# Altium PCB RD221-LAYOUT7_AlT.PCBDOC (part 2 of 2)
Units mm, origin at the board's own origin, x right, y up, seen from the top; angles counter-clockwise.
Board outline 85 x 108 mm, 4 copper layers (TOP, Mid-Layer 1, Mid-Layer 2, BOTTOM), stack 0.711 mm thick; 92 components, 59 nets, 620 pads, 607 vias.
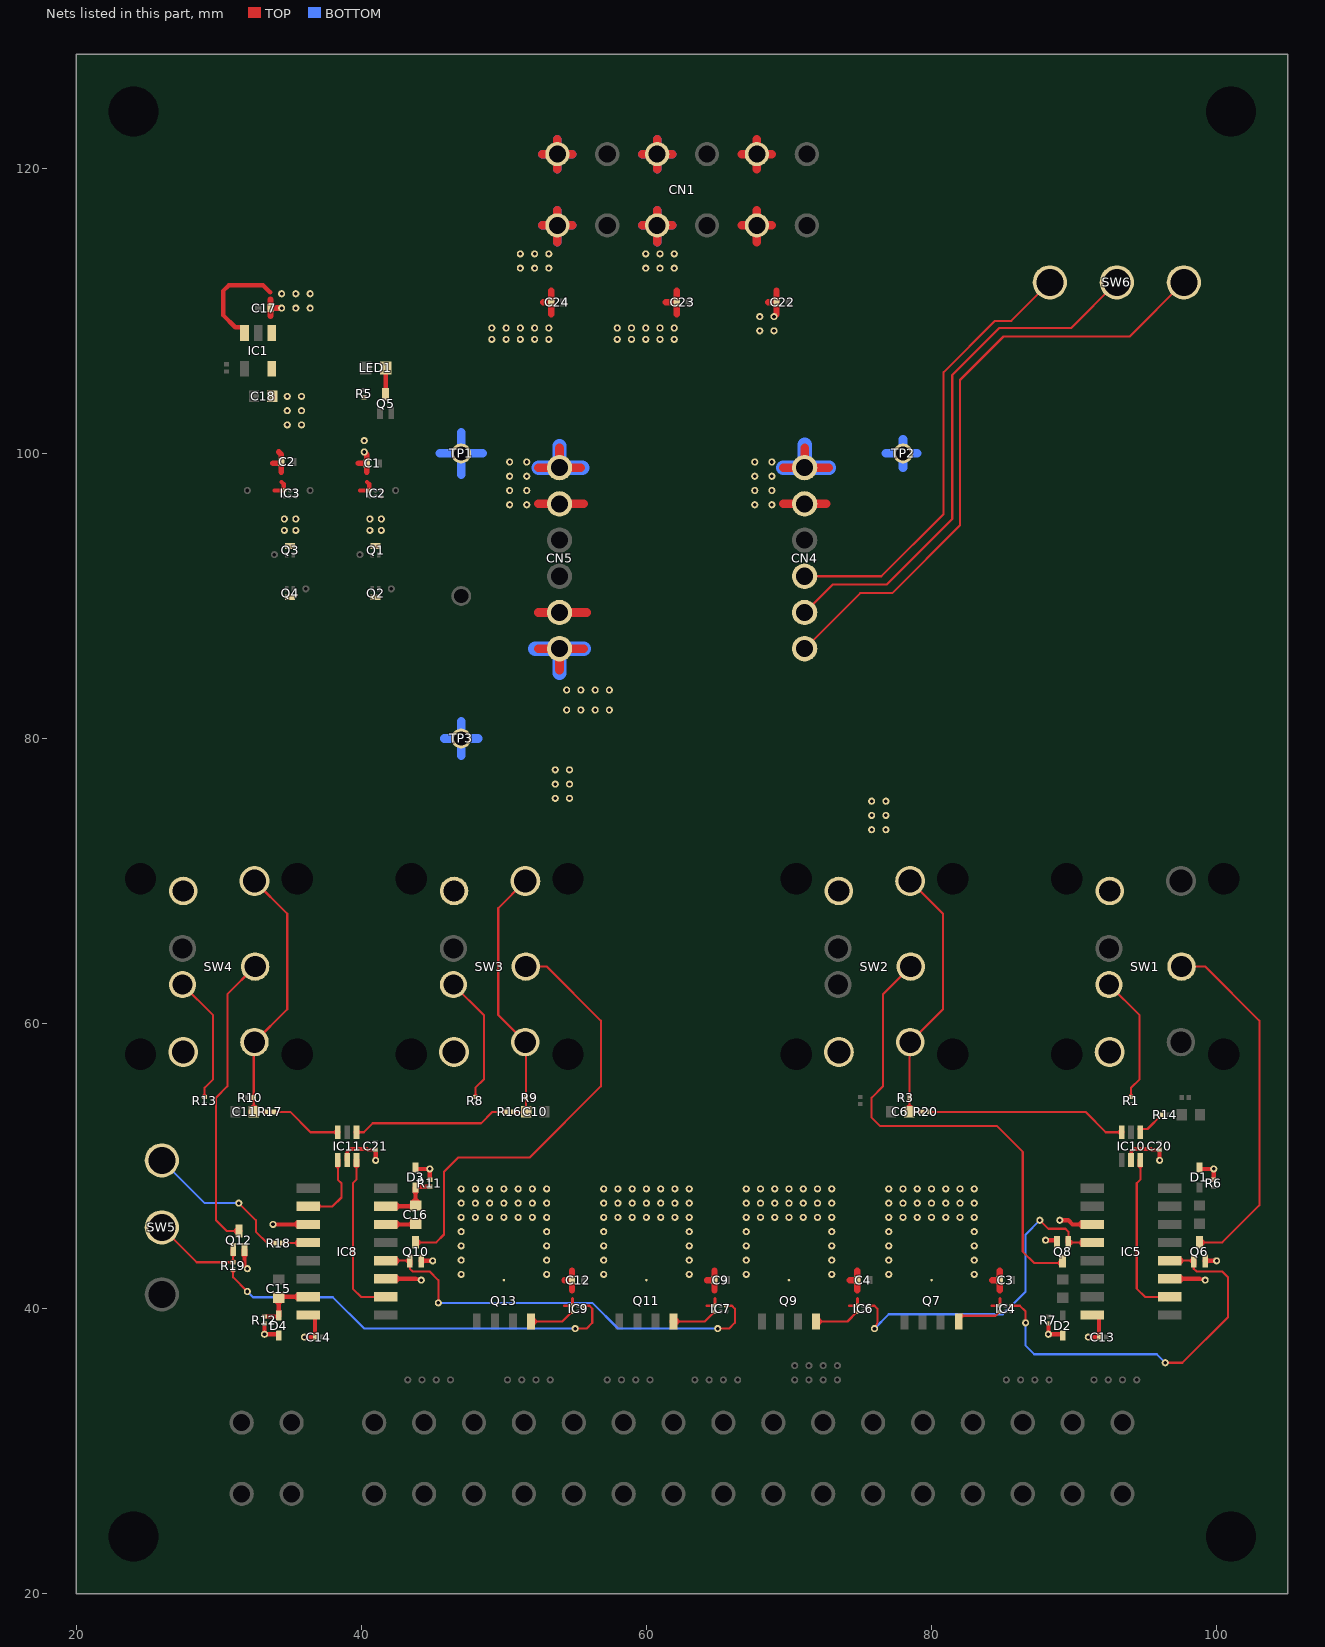
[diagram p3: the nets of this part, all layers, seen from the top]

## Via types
v1: diameter 0.6, hole 0.25, TOP to BOTTOM, 607 vias

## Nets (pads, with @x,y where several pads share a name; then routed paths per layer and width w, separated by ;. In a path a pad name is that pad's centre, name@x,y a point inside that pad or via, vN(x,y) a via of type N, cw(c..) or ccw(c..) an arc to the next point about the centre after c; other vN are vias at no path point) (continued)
SIG313: C6.1 R3.1 R20.1 SW2.2 SW2.4 | length 19
  TOP w0.15: C6.1@78.45,53.964 R3.1@78.45,54.704 ; R3.1@78.45,54.896 78.45,57.4 SW2.2@78.5,58.7 80.8,61 80.8,67.7 SW2.4@78.5,70 ; C6.1@78.554,53.8 R20.1@79.254,53.8
  TOP w0.3: R3.1@78.45,54.704 R3.1@78.45,54.8 R3.1@78.45,54.896 ; R20.1@79.254,53.8 R20.1@79.35,53.8
  TOP w0.7: C6.1@78.44,53.8 C6.1@78.554,53.8 ; C6.1@78.45,53.81 C6.1@78.45,53.964
SIG315: C10.1 R9.1 R16.2 SW3.2 SW3.4 | length 18.7
  TOP w0.15: R16.2@50.746,53.8 C10.1@51.56,53.8 R9.1@51.55,54.8 ; SW3.4@51.5,70 49.6,68.1 49.6,60.6 SW3.2@51.5,58.7 51.55,57.4 R9.1@51.55,54.896
  TOP w0.3: R16.2@50.65,53.8 R16.2@50.746,53.8 ; R9.1@51.55,54.8 R9.1@51.55,54.896
SIG318: C16.1 D3.A IC8.7 R11.2 | length 4.3
  TOP w0.3: IC8.7@42.418,47.175 C16.1@43.594,47.175 ; C16.1@43.8,47.416 D3.A@43.8,48.186 ; D3.A@43.8,48.55 R11.2@44.8,48.55
  TOP w0.4: D3.A@43.8,48.186 D3.A@43.8,48.5
  TOP w0.55: C16.1@43.594,47.175 C16.1@43.8,47.175
  TOP w0.6: IC8.7@41.725,47.175 IC8.7@42.418,47.175
  TOP w0.7: C16.1@43.8,47.24 C16.1@43.8,47.416
SIG321: C16.2 IC8.6 | length 2.1
  TOP w0.3: IC8.6@42.418,45.905 C16.2@43.602,45.905
  TOP w0.6: IC8.6@41.725,45.905 IC8.6@42.418,45.905 ; C16.2@43.602,45.905 C16.2@43.8,45.905
SIG324: IC8.10 IC11.4 | length 5.3
  TOP w0.15: IC8.10@36.868,47.175 37.975,47.175 38.6,47.8 38.6,48.8 38.35,49.05 IC11.4@38.35,50.039
  TOP w0.4: IC11.4@38.35,50.039 IC11.4@38.35,50.425
  TOP w0.6: IC8.10@36.275,47.175 IC8.10@36.868,47.175
SIG326: R13.1 SW4.L2 | length 9
  TOP w0.15: SW4.L2@27.45,62.73 29.6,60.58 29.6,56.097 29,55.497 R13.1@29,54.946
  TOP w0.3: R13.1@29,54.85 R13.1@29,54.946
SIG328: R8.1 SW3.L2 | length 9
  TOP w0.15: SW3.L2@46.45,62.73 48.6,60.58 48.6,56.097 48,55.497 R8.1@48,54.946
  TOP w0.3: R8.1@48,54.85 R8.1@48,54.946
SIG332: C15.2 D4.A IC8.15 R12.2 | length 4.3
  TOP w0.3: R12.2@33.2,39.45 D4.A@34.2,39.45 ; D4.A@34.2,39.814 C15.2@34.2,40.62 ; C15.2@34.406,40.825 IC8.15@35.582,40.825
  TOP w0.4: D4.A@34.2,39.5 D4.A@34.2,39.814
  TOP w0.55: C15.2@34.2,40.825 C15.2@34.406,40.825
  TOP w0.6: IC8.15@35.582,40.825 IC8.15@36.275,40.825
  TOP w0.7: C15.2@34.2,40.62 C15.2@34.2,40.76
SIG333: C11.1 R10.1 R17.1 SW4.2 SW4.4 | length 19
  TOP w0.15: C11.1@32.45,53.964 R10.1@32.45,54.704 ; R10.1@32.45,54.896 32.45,57.4 SW4.2@32.5,58.7 34.8,61 34.8,67.7 SW4.4@32.5,70 ; C11.1@32.554,53.8 R17.1@33.254,53.8
  TOP w0.3: R10.1@32.45,54.704 R10.1@32.45,54.8 R10.1@32.45,54.896 ; R17.1@33.254,53.8 R17.1@33.35,53.8
  TOP w0.7: C11.1@32.44,53.8 C11.1@32.554,53.8 ; C11.1@32.45,53.81 C11.1@32.45,53.964
SIG335: IC8.12 R18.2 | length 1.8
  TOP w0.15: R18.2@34.546,44.6 IC8.12@35.608,44.6
  TOP w0.3: R18.2@34.45,44.6 R18.2@34.546,44.6
  TOP w0.55: IC8.12@35.608,44.6 IC8.12@36.275,44.6
SIG338: IC7.A1 Q11.4 | length 3.2
  TOP w0.15: Q11.4@62.037,39.1 64.1,39.1 IC7.A1@64.8,39.8
  TOP w0.55: Q11.4@61.905,39.1 Q11.4@62.037,39.1
SIG339: IC6.A1 Q9.4 | length 3.2
  TOP w0.15: Q9.4@72.037,39.1 74.1,39.1 IC6.A1@74.8,39.8
  TOP w0.55: Q9.4@71.905,39.1 Q9.4@72.037,39.1
SIG340: IC4.A1 Q7.4 | length 3
  TOP w0.15: Q7.4@82.126,39.5 84.5,39.5 IC4.A1@84.8,39.8
  TOP w0.3: Q7.4@81.905,39.5 Q7.4@82.126,39.5
SIG341: IC9.A1 Q13.4 | length 3.2
  TOP w0.15: Q13.4@52.037,39.1 54.1,39.1 IC9.A1@54.8,39.8
  TOP w0.55: Q13.4@51.905,39.1 Q13.4@52.037,39.1
SIG345: IC10.3 R20.2 | length 14.1
  TOP w0.15: R20.2@79.946,53.8 90.8,53.8 92.225,52.375 IC10.3@93.255,52.375
  TOP w0.3: R20.2@79.85,53.8 R20.2@79.946,53.8
  TOP w0.4: IC10.3@93.255,52.375 IC10.3@93.35,52.375
SIG347: IC9.C2 pad.@32,41.2 pad.@55,38.6 R19.2 | length 29.1
  TOP w0.15: R19.2@31,42.654 31,42.2 pad.@32,41.2 ; pad.@55,38.6 55.8,38.6 56.2,39 56.2,40 56,40.2 IC9.C2@55.6,40.2
  TOP w0.3: R19.2@31,42.654 R19.2@31,42.75
  BOTTOM w0.15: pad.@32,41.2 32.4,40.8 38,40.8 40.2,38.6 pad.@55,38.6
SIG348: pad.@31.4,47.4 R18.1 SW5.1 | length 10.8
  TOP w0.15: pad.@31.4,47.4 32.6,46.2 32.6,45.4 33.4,44.6 R18.1@33.854,44.6
  TOP w0.3: R18.1@33.854,44.6 R18.1@33.95,44.6
  BOTTOM w0.15: SW5.1@26,50.4 29,47.4 pad.@31.4,47.4
SIG3334: LED1.C Q5.C | length 1.8
  TOP w0.3: Q5.C@41.7,104.15 LED1.C@41.7,106
SIG3335: Q6.C SW1.LC | length 25.3
  TOP w0.15: SW1.LC@97.54,64 99.2,64 103,60.2 103,47.25 100.4,44.65 Q6.C@98.925,44.65
  TOP w0.5: Q6.C@98.8,44.65 Q6.C@98.925,44.65
SIG3337: Q8.C SW2.LC | length 33.5
  TOP w0.15: SW2.LC@78.54,64 76.6,62.06 76.6,55.6 75.8,54.8 75.8,53.4 76.4,52.8 84.6,52.8 86.4,51 86.4,44 87.2,43.2 Q8.C@89.075,43.2
  TOP w0.5: Q8.C@89.075,43.2 Q8.C@89.2,43.2
SIG3338: Q10.C SW3.LC | length 31.5
  TOP w0.15: Q10.C@43.925,44.65 45.25,44.65 45.8,45.2 45.8,49.6 46.8,50.6 51.8,50.6 56.8,55.6 56.8,60.2 53,64 SW3.LC@51.54,64
  TOP w0.5: Q10.C@43.8,44.65 Q10.C@43.925,44.65
SIG3340: Q12.C SW4.LC | length 20.8
  TOP w0.15: Q12.C@31.275,45.45 30.55,45.45 29.8,46.2 29.8,54.8 30.6,55.6 30.6,62.06 SW4.LC@32.54,64
  TOP w0.5: Q12.C@31.275,45.45 Q12.C@31.4,45.45
SIG3348: R1.1 SW1.L2 | length 9
  TOP w0.15: SW1.L2@92.45,62.73 94.6,60.58 94.6,56.097 94,55.497 R1.1@94,54.946
  TOP w0.3: R1.1@94,54.85 R1.1@94,54.946
SIG3352: IC5.2 IC10.6 | length 11.7
  TOP w0.15: IC10.6@94.65,50.039 94.65,49.05 94.4,48.8 94.4,41.4 94.975,40.825 IC5.2@96.225,40.825
  TOP w0.4: IC10.6@94.65,50.039 IC10.6@94.65,50.425
  TOP w0.6: IC5.2@96.225,40.825 IC5.2@96.725,40.825
SIG3353: IC10.1 R14.1 | length 2
  TOP w0.15: IC10.1@94.715,52.6 95.15,52.6 R14.1@96.15,53.6
  TOP w0.3: IC10.1@94.6,52.6 IC10.1@94.715,52.6
SIG3354: IC8.2 IC11.6 | length 11.7
  TOP w0.15: IC11.6@39.65,50.039 39.65,49.05 39.4,48.8 39.4,41.4 39.975,40.825 IC8.2@41.225,40.825
  TOP w0.4: IC11.6@39.65,50.039 IC11.6@39.65,50.425
  TOP w0.6: IC8.2@41.225,40.825 IC8.2@41.725,40.825
SIG3355: IC11.1 R16.1 | length 11.1
  TOP w0.15: IC11.1@39.745,52.375 40.175,52.375 40.8,53 48.4,53 49.2,53.8 R16.1@50.054,53.8
  TOP w0.3: R16.1@50.054,53.8 R16.1@50.15,53.8
  TOP w0.4: IC11.1@39.65,52.375 IC11.1@39.745,52.375
SIG3356: IC11.3 R17.2 | length 5.1
  TOP w0.15: R17.2@33.946,53.8 35,53.8 36.425,52.375 IC11.3@38.239,52.375
  TOP w0.3: R17.2@33.85,53.8 R17.2@33.946,53.8
  TOP w0.4: IC11.3@38.239,52.375 IC11.3@38.35,52.375
SIG3359: CN4.3 SW6.3 | length 31.6
  TOP w0.15: CN4.3@71.1,91.38 76.48,91.38 80.85,95.75 80.85,105.7 84.45,109.3 85.6,109.3 SW6.3@88.3,112
SIG3360: CN4.2 SW6.2 | length 37.4
  TOP w0.15: CN4.2@71.1,88.84 73.06,90.8 76.85,90.8 81.45,95.4 81.45,105.5 84.75,108.8 89.8,108.8 SW6.2@93,112
SIG3361: CN4.1 SW6.1 | length 43.2
  TOP w0.15: CN4.1@71.1,86.3 75,90.2 77.25,90.2 82,94.95 82,105.15 85.05,108.2 93.9,108.2 SW6.1@97.7,112
SW_CONTA: IC4.C2 IC5.4 pad.@86.6,39 pad.@96.4,36.2 Q6.B | length 27.2
  TOP w0.15: IC4.C2@85.6,40.2 86.2,40.2 86.6,39.8 pad.@86.6,39 ; pad.@96.4,36.2 97.6,36.2 100.8,39.4 100.8,42.2 100.4,42.6 98.6,42.6 98.4,42.8 Q6.B@98.4,43.1 ; IC5.4@97.364,43.365 Q6.B@98.279,43.365
  TOP w0.37: Q6.B@98.279,43.365 Q6.B@98.385,43.365
  TOP w0.4: Q6.B@98.4,43.1 Q6.B@98.4,43.35
  TOP w0.6: IC5.4@96.725,43.365 IC5.4@97.364,43.365
  BOTTOM w0.15: pad.@86.6,39 86.6,37.4 87.2,36.8 95.8,36.8 pad.@96.4,36.2
SW_CONTB: IC5.12 IC6.C2 pad.@76,38.6 pad.@87.6,46.2 Q8.B | length 24
  TOP w0.15: IC6.C2@75.6,40.2 76,40.2 76.2,40 76.2,39 pad.@76,38.6 ; pad.@87.6,46.2 88.2,45.6 89.4,45.6 89.6,45.4 Q8.B@89.6,44.9 ; Q8.B@89.711,44.635 IC5.12@90.636,44.635
  TOP w0.4: Q8.B@89.6,44.635 Q8.B@89.711,44.635 ; Q8.B@89.6,44.65 Q8.B@89.6,44.9
  TOP w0.6: IC5.12@90.636,44.635 IC5.12@91.275,44.635
  BOTTOM w0.15: pad.@76,38.6 77,39.6 85,39.6 86.6,41.2 86.6,45.2 pad.@87.6,46.2
SW_CONTC: IC7.C2 IC8.4 pad.@45.4,40.4 pad.@65,38.6 Q10.B | length 29.6
  TOP w0.15: IC8.4@42.364,43.365 Q10.B@43.289,43.365 ; Q10.B@43.4,43.1 43.4,42.8 43.6,42.6 44.8,42.6 45.4,42 pad.@45.4,40.4 ; pad.@65,38.6 65.8,38.6 66.2,39 66.2,40 66,40.2 IC7.C2@65.6,40.2
  TOP w0.4: Q10.B@43.289,43.365 Q10.B@43.4,43.365 ; Q10.B@43.4,43.1 Q10.B@43.4,43.35
  TOP w0.6: IC8.4@41.725,43.365 IC8.4@42.364,43.365
  BOTTOM w0.15: pad.@45.4,40.4 56.2,40.4 58,38.6 pad.@65,38.6
SW_CONTD: Q12.B R19.1 SW5.2 | length 6.9
  TOP w0.15: SW5.2@26,45.7 28.45,43.25 R19.1@30.904,43.25 ; R19.1@31,43.346 Q12.B@31,43.836
  TOP w0.3: R19.1@30.904,43.25 R19.1@31,43.25 R19.1@31,43.346
  TOP w0.4: Q12.B@31,43.836 Q12.B@31,44.15
VDD: C17.1 C22.1 CN1.5 CN1.5A IC1.1 IC1.3 pad.@34.4,110.2 pad.@34.4,111.2 pad.@35.4,110.2 pad.@35.4,111.2 pad.@36.4,110.2 pad.@36.4,111.2 pad.@67.95,108.6 pad.@67.95,109.6 pad.@68.95,108.6 pad.@68.95,109.6 | length 19.9
  TOP w0.3: IC1.3@31.78,108.85 31.15,108.85 30.3,109.7 30.3,111.4 30.7,111.8 33.1,111.8 33.6,111.3
  TOP w0.45: 33.625,109.65 C17.1@33.625,110.2 ; 33.625,110.8 C17.1@33.625,110.2 ; pad.@34.4,110.2 C17.1@33.625,110.2 ; 68.55,110.6 C22.1@69.125,110.6 ; pad.@69.125,109.775 C22.1@69.125,110.6 ; 69.125,111.425 C22.1@69.125,110.6
  TOP w0.6: 66.7,116 CN1.5@67.75,116 ; 66.7,121 CN1.5A@67.75,121 ; 67.75,114.8 CN1.5@67.75,116 ; 67.75,117.05 CN1.5@67.75,116 ; 67.75,119.95 CN1.5A@67.75,121 ; 67.75,122.05 CN1.5A@67.75,121 ; 68.8,116 CN1.5@67.75,116 ; 68.8,121 CN1.5A@67.75,121
VINA: C1.1 C24.1 CN1.1 CN1.1A CN5.1 CN5.2 IC2.A2 pad.@40.2,100.1 pad.@40.2,100.9 pad.@40.6,94.6 pad.@40.6,95.4 pad.@41.4,94.6 pad.@41.4,95.4 pad.@49.15,108 pad.@49.15,108.8 pad.@50.4,96.4 pad.@50.4,97.4 pad.@50.4,98.4 pad.@50.4,99.4 pad.@50.15,108 pad.@50.15,108.8 pad.@51.6,96.4 pad.@51.6,97.4 pad.@51.6,98.4 pad.@51.6,99.4 pad.@51.15,108 pad.@51.15,108.8 pad.@51.15,113 pad.@51.15,114 pad.@52.15,108 pad.@52.15,108.8 pad.@52.15,113 pad.@52.15,114 pad.@53.15,108 pad.@53.15,108.8 pad.@53.15,113 pad.@53.15,114 Q1.D TP1.1 | length 40.9
  TOP w0.3: 39.9,97.4 IC2.A2@40.6,97.4 40.55,97.45 40.55,97.85 40.4,98
  TOP w0.4: 39.8,99.3 C1.1@40.375,99.3 ; pad.@40.2,100.1 40.375,99.925 C1.1@40.375,99.3 ; 40.375,98.7 C1.1@40.375,99.3
  TOP w0.45: 52.75,110.6 C24.1@53.325,110.6 ; 53.325,109.775 C24.1@53.325,110.6 ; 53.325,111.425 C24.1@53.325,110.6
  TOP w0.6: 52.4,96.46 CN5.2@53.9,96.46 55.6,96.46 ; 52.4,99 CN5.1@53.9,99 ; 52.7,116 CN1.1@53.75,116 ; 52.7,121 CN1.1A@53.75,121 ; 53.75,114.8 CN1.1@53.75,116 ; 53.75,117.05 CN1.1@53.75,116 ; 53.75,119.95 CN1.1A@53.75,121 ; 53.75,122.05 CN1.1A@53.75,121 ; 53.9,100.4 CN5.1@53.9,99 ; 54.8,116 CN1.1@53.75,116 ; 54.8,121 CN1.1A@53.75,121 ; 55.4,99 CN5.1@53.9,99
  BOTTOM w0.6: 45.5,100 TP1.1@47,100 ; 47,98.5 TP1.1@47,100 ; 47,101.5 TP1.1@47,100 ; 48.5,100 TP1.1@47,100 ; 52.7,116 CN1.1@53.75,116 ; 52.7,121 CN1.1A@53.75,121 ; 53.75,114.8 CN1.1@53.75,116 ; 53.75,117.05 CN1.1@53.75,116 ; 53.75,119.95 CN1.1A@53.75,121 ; 53.75,122.05 CN1.1A@53.75,121 ; 54.8,116 CN1.1@53.75,116 ; 54.8,121 CN1.1A@53.75,121
  BOTTOM w1: 52.45,99 CN5.1@53.9,99 ; 53.9,100.525 CN5.1@53.9,99 ; 55.5,99 CN5.1@53.9,99
VINB: C23.1 CN1.3 CN1.3A CN4.5 CN4.6 pad.@57.95,108 pad.@57.95,108.8 pad.@58.95,108 pad.@58.95,108.8 pad.@59.95,108 pad.@59.95,108.8 pad.@59.95,113 pad.@59.95,114 pad.@60.95,108 pad.@60.95,108.8 pad.@60.95,113 pad.@60.95,114 pad.@61.95,108 pad.@61.95,108.8 pad.@61.95,113 pad.@61.95,114 pad.@67.6,96.4 pad.@67.6,97.4 pad.@67.6,98.4 pad.@67.6,99.4 pad.@68.8,96.4 pad.@68.8,97.4 pad.@68.8,98.4 pad.@68.8,99.4 TP2.1 | length 36.1
  TOP w0.45: 61.35,110.6 C23.1@62.125,110.6 ; 62.125,109.775 C23.1@62.125,110.6 ; 62.125,111.425 C23.1@62.125,110.6
  TOP w0.6: 59.7,116 CN1.3@60.75,116 ; 59.7,121 CN1.3A@60.75,121 ; 60.75,114.8 CN1.3@60.75,116 ; 60.75,117.05 CN1.3@60.75,116 ; 60.75,119.95 CN1.3A@60.75,121 ; 60.75,122.05 CN1.3A@60.75,121 ; 61.8,116 CN1.3@60.75,116 ; 61.8,121 CN1.3A@60.75,121 ; 69.6,96.46 CN4.5@71.1,96.46 72.6,96.46 ; 69.6,99 CN4.6@71.1,99 ; 71.1,100.4 CN4.6@71.1,99 ; 72.8,99 CN4.6@71.1,99
  BOTTOM w0.6: 59.7,116 CN1.3@60.75,116 ; 59.7,121 CN1.3A@60.75,121 ; 60.75,114.8 CN1.3@60.75,116 ; 60.75,117.05 CN1.3@60.75,116 ; 60.75,119.95 CN1.3A@60.75,121 ; 60.75,122.05 CN1.3A@60.75,121 ; 61.8,116 CN1.3@60.75,116 ; 61.8,121 CN1.3A@60.75,121 ; 76.8,100 TP2.1@78,100 ; 78,99 TP2.1@78,100 ; 78,101 TP2.1@78,100 ; 79,100 TP2.1@78,100
  BOTTOM w1: 69.6,99 CN4.6@71.1,99 ; 71.1,100.6 CN4.6@71.1,99 ; 72.8,99 CN4.6@71.1,99
VOUT: C3.1 C4.1 C9.1 C12.1 CN5.5 CN5.6 IC4.A2 IC6.A2 IC7.A2 IC9.A2 pad.@47,42.4 pad.@47,43.4 pad.@47,44.4 pad.@47,45.4 pad.@47,46.4 pad.@47,47.4 pad.@47,48.4 pad.@48,46.4 pad.@48,47.4 pad.@48,48.4 pad.@49,46.4 pad.@49,47.4 pad.@49,48.4 pad.@50,46.4 pad.@50,47.4 pad.@50,48.4 pad.@51,46.4 pad.@51,47.4 pad.@51,48.4 pad.@52,46.4 pad.@52,47.4 pad.@52,48.4 pad.@53,42.4 pad.@53,43.4 pad.@53,44.4 pad.@53,45.4 pad.@53,46.4 pad.@53,47.4 pad.@53,48.4 pad.@54.4,82 pad.@54.4,83.4 pad.@55.4,82 pad.@55.4,83.4 pad.@56.4,82 pad.@56.4,83.4 pad.@57,42.4 pad.@57,43.4 pad.@57,44.4 pad.@57,45.4 pad.@57,46.4 pad.@57,47.4 pad.@57,48.4 pad.@57.4,82 pad.@57.4,83.4 pad.@58,46.4 pad.@58,47.4 pad.@58,48.4 pad.@59,46.4 pad.@59,47.4 pad.@59,48.4 pad.@60,46.4 pad.@60,47.4 pad.@60,48.4 pad.@61,46.4 pad.@61,47.4 pad.@61,48.4 pad.@62,46.4 pad.@62,47.4 pad.@62,48.4 pad.@63,42.4 pad.@63,43.4 pad.@63,44.4 pad.@63,45.4 pad.@63,46.4 pad.@63,47.4 pad.@63,48.4 pad.@67,42.4 pad.@67,43.4 pad.@67,44.4 pad.@67,45.4 pad.@67,46.4 pad.@67,47.4 pad.@67,48.4 pad.@68,46.4 pad.@68,47.4 pad.@68,48.4 pad.@69,46.4 pad.@69,47.4 pad.@69,48.4 pad.@70,46.4 pad.@70,47.4 pad.@70,48.4 pad.@71,46.4 pad.@71,47.4 pad.@71,48.4 pad.@72,46.4 pad.@72,47.4 pad.@72,48.4 pad.@73,42.4 pad.@73,43.4 pad.@73,44.4 pad.@73,45.4 pad.@73,46.4 pad.@73,47.4 pad.@73,48.4 pad.@77,42.4 pad.@77,43.4 pad.@77,44.4 pad.@77,45.4 pad.@77,46.4 pad.@77,47.4 pad.@77,48.4 pad.@78,46.4 pad.@78,47.4 pad.@78,48.4 pad.@79,46.4 pad.@79,47.4 pad.@79,48.4 pad.@80,46.4 pad.@80,47.4 pad.@80,48.4 pad.@81,46.4 pad.@81,47.4 pad.@81,48.4 pad.@82,46.4 pad.@82,47.4 pad.@82,48.4 pad.@83,42.4 pad.@83,43.4 pad.@83,44.4 pad.@83,45.4 pad.@83,46.4 pad.@83,47.4 pad.@83,48.4 Q7.5 Q9.5 Q11.5 Q13.5 TP3.1 | length 29.7
  TOP w0.2: 54.25,40.2 IC9.A2@54.8,40.2 54.8,40.7 ; 64.25,40.2 IC7.A2@64.8,40.2 64.8,40.7 ; 74.25,40.2 IC6.A2@74.8,40.2 74.8,40.7 ; 84.25,40.2 IC4.A2@84.8,40.2 84.8,40.7
  TOP w0.45: 54.25,42 C12.1@54.775,42 ; 54.775,41.3 C12.1@54.775,42 ; 54.775,42.65 C12.1@54.775,42 ; 64.25,42 C9.1@64.775,42 ; 64.775,41.3 C9.1@64.775,42 ; 64.775,42.65 C9.1@64.775,42 ; 74.25,42 C4.1@74.775,42 ; 74.775,41.3 C4.1@74.775,42 ; 74.775,42.65 C4.1@74.775,42 ; 84.25,42 C3.1@84.775,42 ; 84.775,41.3 C3.1@84.775,42 ; 84.775,42.65 C3.1@84.775,42
  TOP w0.6: 52.4,86.3 CN5.6@53.9,86.3 ; 52.4,88.84 CN5.5@53.9,88.84 55.8,88.84 ; 53.9,84.8 CN5.6@53.9,86.3 ; 55.6,86.3 CN5.6@53.9,86.3
  BOTTOM w0.6: 45.8,80 TP3.1@47,80 ; 47,78.8 TP3.1@47,80 ; 47,81.2 TP3.1@47,80 ; 48.2,80 TP3.1@47,80
  BOTTOM w1: 52.2,86.3 CN5.6@53.9,86.3 ; 53.9,84.6 CN5.6@53.9,86.3 ; 55.6,86.3 CN5.6@53.9,86.3
VP_4R8: C2.1 C13.2 C14.2 C18.1 C20.2 C21.2 D1.C D2.C D3.C D4.C IC1.5 IC3.A2 IC5.3 IC5.11 IC5.16 IC8.3 IC8.11 IC8.16 IC10.5 IC11.5 pad.@32,42.8 pad.@33.2,38.2 pad.@33.8,45.905 pad.@34.6,94.6 pad.@34.6,95.4 pad.@34.8,102 pad.@34.8,103 pad.@34.8,104 pad.@35.4,94.6 pad.@35.4,95.4 pad.@35.8,102 pad.@35.8,103 pad.@35.8,104 pad.@36,38 pad.@41,50.4 pad.@44.2,42 pad.@44.8,49.8 pad.@45,43.35 pad.@53.6,75.8 pad.@53.6,76.8 pad.@53.6,77.8 pad.@54.6,75.8 pad.@54.6,76.8 pad.@54.6,77.8 pad.@75.8,73.6 pad.@75.8,74.6 pad.@75.8,75.6 pad.@76.8,73.6 pad.@76.8,74.6 pad.@76.8,75.6 pad.@88,44.8 pad.@88.2,38.2 pad.@89,46.2 pad.@91,38 pad.@96,50.4 pad.@99.2,42 pad.@99.8,49.8 pad.@100,43.35 Q3.D Q6.E Q8.E Q10.E Q12.E R5.2 R6.1 R7.1 R11.1 R12.1 SW1.1 SW1.3 SW2.1 SW2.3 SW3.1 SW3.3 SW4.1 SW4.3 | length 35.6
  TOP w0.25: IC11.5@39,50.7 39,51 39.2,51.2 40.4,51.2 40.45,51.15 C21.2@40.868,51.15 ; IC10.5@94,50.7 94,51 94.2,51.2 95.4,51.2 95.45,51.15 C20.2@95.868,51.15
  TOP w0.3: Q12.E@31.8,43.736 31.8,43 pad.@32,42.8 ; R12.1@33.2,38.95 pad.@33.2,38.2 D4.C@34.2,38.2 ; pad.@33.8,45.905 IC8.11@35.582,45.905 ; 33.9,97.4 IC3.A2@34.6,97.4 34.55,97.45 34.55,97.85 34.4,98 ; pad.@36,38 C14.2@36.75,38 IC8.16@36.75,39.555 ; C21.2@40.868,51.15 C21.2@41,51.15 pad.@41,50.4 ; IC8.3@42.418,42.095 43.8,42.095 43.859,42.081 pad.@44.2,42 ; D3.C@43.8,49.8 pad.@44.8,49.8 R11.1@44.8,49.05 ; Q10.E@44.364,43.35 pad.@45,43.35 ; pad.@88,44.8 Q8.E@88.8,44.8 ; R7.1@88.2,38.95 pad.@88.2,38.2 D2.C@89.2,38.2 ; pad.@89,46.2 89.6,46.2 89.895,45.905 IC5.11@90.582,45.905 ; pad.@91,38 C13.2@91.75,38 IC5.16@91.75,39.555 ; C20.2@95.868,51.15 C20.2@96,51.15 pad.@96,50.4 ; IC5.3@97.418,42.095 98.8,42.095 98.859,42.081 pad.@99.2,42 ; D1.C@98.8,49.8 pad.@99.8,49.8 R6.1@99.8,49.05 ; Q6.E@99.364,43.35 pad.@100,43.35
  TOP w0.4: Q12.E@31.8,43.736 Q12.E@31.8,44.15 ; 33.8,99.3 C2.1@34.375,99.3 ; 34.2,100.1 34.375,99.925 C2.1@34.375,99.4 C2.1@34.375,99.3 ; 34.375,98.7 C2.1@34.375,99.3 ; IC11.5@39,50.425 IC11.5@39,50.7 ; Q10.E@44.2,43.35 Q10.E@44.364,43.35 ; IC10.5@94,50.425 IC10.5@94,50.7 ; Q6.E@99.2,43.35 Q6.E@99.364,43.35
  TOP w0.6: IC8.11@35.582,45.905 IC8.11@36.275,45.905 ; IC8.3@41.725,42.095 IC8.3@42.418,42.095 ; IC5.11@90.582,45.905 IC5.11@91.275,45.905 ; IC5.3@96.725,42.095 IC5.3@97.418,42.095
VP_SW: Q2.D Q4.D
pads on no net: cam1. cam2. cam4. cam5. IC2.C1 IC3.C1 IC4.B1 IC4.C1 IC5.5 IC5.13 IC6.B1 IC6.C1 IC7.B1 IC7.C1 IC8.5 IC8.13 IC9.B1 IC9.C1 SW1. SW1.L1 SW2. SW2.L1 SW3. SW3.L1 SW4. SW4.L1

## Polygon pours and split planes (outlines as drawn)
no net on Top Overlay "TOPOVERLAY97" (solid, pour order 0): 24.6,80.2 23.6,81.2 25.6,81.2
no net on Top Overlay "TOPOVERLAY96" (solid, pour order 0): 24.6,83.4 25.6,82.4 23.6,82.4
no net on Top Overlay "TOPOVERLAY95" (solid, pour order 0): 94.306,102.487 93.306,101.487 93.306,103.487
no net on Top Overlay "TOPOVERLAY94" (solid, pour order 0): 91.206,102.487 92.206,103.487 92.206,101.487
no net on Top Overlay "TOPOVERLAY93" (solid, pour order 0): 53.1,104.9 54.9,104.9 54,103.1
no net on Top Overlay "TOPOVERLAY100" (solid, pour order 0): 97.688,91.502 98.51,94.216 99.643,94.216 100.465,91.502 99.668,91.502 99.522,92.005 98.631,92.005 98.485,91.502
no net on Top Overlay "TOPOVERLAY99" (solid, pour order 0): 120 vertices, not listed, extent 95.148,91.502 97.493,94.216
no net on Top Overlay "TOPOVERLAY98" (solid, pour order 0): 147 vertices, not listed, extent 84.708,91.454 87.279,94.264
VP_4R8 on TOP "TOP54" (solid, pour order 93): 48 vertices, not listed, extent 33.4,97.25 40.4,106.5
GND on TOP "TOP53" (solid, pour order 92): 31 vertices, not listed, extent 20.5,20.5 104.5,127.5
VINB on TOP "TOP15" (solid, pour order 54): 19 vertices, not listed, extent 67,95.75 74,102
VOUT on TOP "TOP52" (solid, pour order 91): 141 vertices, not listed, extent 49.8,40.1 85,89.45
VP_4R8 on TOP "TOP26" (solid, pour order 65): 17 vertices, not listed, extent 53.2,73 77.2,78.2
VP_SW on TOP "TOP51" (solid, pour order 90): 42 vertices, not listed, extent 33.8,83 42.2,90.1
GND on TOP "TOP49" (solid, pour order 88): 99 vertices, not listed, extent 71.768,33.05 84,49.85
LOADA on TOP "TOP48" (solid, pour order 87): 43 vertices, not listed, extent 77,25.2 95.65,39.6
GND on TOP "TOP47" (solid, pour order 86): 86 vertices, not listed, extent 61.562,33.05 73.85,49.85
GND on TOP "TOP46" (solid, pour order 85): 89 vertices, not listed, extent 51.55,33.05 63.85,49.85
LOADB on TOP "TOP45" (solid, pour order 84): 51 vertices, not listed, extent 67,25.2 81.65,39.65
GND on TOP "TOP44" (solid, pour order 83): 75.952,33.049 cw(c75.952,33.124) 75.948,33.049 ccw(c75.9,32) 75.9,33.05 74.875,33.05 cw(c74.875,33.125) 74.8,33.125 74.8,33.697 cw(c75.05,33.696) 74.873,33.873 74.877,33.877 cw(c75.054,33.7) 75.054,33.95 76.746,33.95 cw(c76.746,33.7) 76.923,33.877 76.927,33.873 cw(c76.75,33.696) 77,33.696 77,33.299 cw(c76.75,33.299) 76.75,33.049
LOADC on TOP "TOP43" (solid, pour order 82): 36 vertices, not listed, extent 56.15,25.2 67.65,39.65
LOADD on TOP "TOP42" (solid, pour order 81): 34 vertices, not listed, extent 42.15,25.2 53.65,39.65
GND on TOP "TOP41" (solid, pour order 80): 89.952,33.049 cw(c89.952,33.124) 89.948,33.049 ccw(c89.9,32) 89.9,33.05 88.875,33.05 cw(c88.875,33.125) 88.8,33.125 88.8,33.95 cw(c88.9,33.95) 88.9,34.05 90.9,34.05 cw(c90.9,33.95) 91,33.95 91,33.299 cw(c90.75,33.299) 90.75,33.049
GND on TOP "TOP40" (solid, pour order 79): 61.952,33.049 cw(c61.952,33.124) 61.948,33.049 ccw(c61.9,32) 61.9,33.05 60.875,33.05 cw(c60.875,33.125) 60.8,33.125 60.8,33.95 cw(c60.9,33.95) 60.9,34.05 62.9,34.05 cw(c62.9,33.95) 63,33.95 63,33.299 cw(c62.75,33.299) 62.75,33.049
GND on TOP "TOP39" (solid, pour order 78): 89.05,28.05 cw(c89.05,28.3) 88.8,28.3 88.8,30.7 cw(c89.05,30.7) 89.05,30.95 90.75,30.95 cw(c90.75,30.7) 91,30.7 91,28.3 cw(c90.75,28.3) 90.75,28.05
GND on TOP "TOP38" (solid, pour order 77): 82.05,28.05 cw(c82.05,28.3) 81.8,28.3 81.8,30.7 cw(c82.05,30.7) 82.05,30.95 83.75,30.95 cw(c83.75,30.7) 84,30.7 84,28.3 cw(c83.75,28.3) 83.75,28.05
GND on TOP "TOP37" (solid, pour order 76): 75.05,28.05 cw(c75.05,28.3) 74.8,28.3 74.8,30.7 cw(c75.05,30.7) 75.05,30.95 76.75,30.95 cw(c76.75,30.7) 77,30.7 77,28.3 cw(c76.75,28.3) 76.75,28.05
GND on TOP "TOP36" (solid, pour order 75): 68.05,28.05 cw(c68.05,28.3) 67.8,28.3 67.8,30.7 cw(c68.05,30.7) 68.05,30.95 69.75,30.95 cw(c69.75,30.7) 70,30.7 70,28.3 cw(c69.75,28.3) 69.75,28.05
GND on TOP "TOP35" (solid, pour order 74): 61.05,28.05 cw(c61.05,28.3) 60.8,28.3 60.8,30.7 cw(c61.05,30.7) 61.05,30.95 62.75,30.95 cw(c62.75,30.7) 63,30.7 63,28.3 cw(c62.75,28.3) 62.75,28.05
GND on TOP "TOP34" (solid, pour order 73): 54.05,28.05 cw(c54.05,28.3) 53.8,28.3 53.8,30.7 cw(c54.05,30.7) 54.05,30.95 55.75,30.95 cw(c55.75,30.7) 56,30.7 56,28.3 cw(c55.75,28.3) 55.75,28.05
GND on TOP "TOP33" (solid, pour order 72): 47.05,28.05 cw(c47.05,28.3) 46.8,28.3 46.8,30.7 cw(c47.05,30.7) 47.05,30.95 48.75,30.95 cw(c48.75,30.7) 49,30.7 49,28.3 cw(c48.75,28.3) 48.75,28.05
GND on TOP "TOP32" (solid, pour order 71): 47.952,33.049 cw(c47.952,33.124) 47.948,33.049 ccw(c47.9,32) 47.9,33.05 46.875,33.05 cw(c46.875,33.125) 46.8,33.125 46.8,33.95 cw(c46.9,33.95) 46.9,34.05 48.9,34.05 cw(c48.9,33.95) 49,33.95 49,33.299 cw(c48.75,33.299) 48.75,33.049
GND on TOP "TOP28" (solid, pour order 67): 104 vertices, not listed, extent 34.75,88.15 42.175,105.4
VOUT on TOP "TOP19" (solid, pour order 58): 46.95,42 cw(c46.95,42.25) 46.7,42.25 46.7,48.55 cw(c46.95,48.55) 46.95,48.8 53.05,48.8 cw(c53.05,48.55) 53.3,48.55 53.3,42.25 cw(c53.05,42.25) 53.05,42
VOUT on TOP "TOP18" (solid, pour order 57): 76.95,42 cw(c76.95,42.25) 76.7,42.25 76.7,48.55 cw(c76.95,48.55) 76.95,48.8 83.05,48.8 cw(c83.05,48.55) 83.3,48.55 83.3,42.25 cw(c83.05,42.25) 83.05,42
VOUT on TOP "TOP17" (solid, pour order 56): 66.95,42 cw(c66.95,42.25) 66.7,42.25 66.7,48.55 cw(c66.95,48.55) 66.95,48.8 73.05,48.8 cw(c73.05,48.55) 73.3,48.55 73.3,42.25 cw(c73.05,42.25) 73.05,42
VOUT on TOP "TOP16" (solid, pour order 55): 56.95,42 cw(c56.95,42.25) 56.7,42.25 56.7,48.55 cw(c56.95,48.55) 56.95,48.8 63.05,48.8 cw(c63.05,48.55) 63.3,48.55 63.3,42.25 cw(c63.05,42.25) 63.05,42
VP_SW on TOP "TOP6" (solid, pour order 45): 41.725,90.1 cw(c41.725,90.025) 41.8,90.025 41.8,89.775 cw(c41.725,89.775) 41.725,89.7 41.3,89.7 41.3,89.375 cw(c41.225,89.375) 41.225,89.3 40.775,89.3 cw(c40.775,89.375) 40.7,89.375 40.7,89.7 40.275,89.7 cw(c40.275,89.775) 40.2,89.775 40.2,90.025 cw(c40.275,90.025) 40.275,90.1
VINA on TOP "TOP14" (solid, pour order 53): 19 vertices, not listed, extent 49.8,95.75 56.8,102
GND on TOP "TOP50" (solid, pour order 89): 17 vertices, not listed, extent 37,106 77,127.5
GND on TOP "TOP24" (solid, pour order 63): 32.175,103.05 cw(c32.175,103.125) 32.1,103.125 32.1,103.6 31.225,103.6 cw(c31.225,103.675) 31.15,103.675 31.15,104.325 cw(c31.225,104.325) 31.225,104.4 32.1,104.4 32.1,104.825 cw(c32.175,104.825) 32.175,104.9 32.725,104.9 cw(c32.725,104.825) 32.8,104.825 32.8,103.125 cw(c32.725,103.125) 32.725,103.05
VP_4R8 on TOP "TOP23" (solid, pour order 62): 33.475,103.05 cw(c33.475,103.125) 33.4,103.125 33.4,104.825 cw(c33.475,104.825) 33.475,104.9 34.025,104.9 cw(c34.025,104.825) 34.1,104.825 34.1,104.4 34.975,104.4 cw(c34.975,104.325) 35.05,104.325 35.05,103.675 cw(c34.975,103.675) 34.975,103.6 34.1,103.6 34.1,103.125 cw(c34.025,103.125) 34.025,103.05
VP_4R8 on TOP "TOP21" (solid, pour order 60): 33.475,104.7 cw(c33.475,104.775) 33.4,104.775 33.4,106.425 cw(c33.475,106.425) 33.475,106.5 34.525,106.5 cw(c34.525,106.425) 34.6,106.425 34.6,105.475 cw(c34.525,105.475) 34.525,105.4 34,105.4 34,104.775 cw(c33.925,104.775) 33.925,104.7
VP_4R8 on TOP "TOP13" (solid, pour order 52): 34.275,93.3 cw(c34.275,93.375) 34.2,93.375 34.2,93.625 cw(c34.275,93.625) 34.275,93.7 34.7,93.7 34.7,94.025 cw(c34.775,94.025) 34.775,94.1 35.225,94.1 cw(c35.225,94.025) 35.3,94.025 35.3,93.7 35.725,93.7 cw(c35.725,93.625) 35.8,93.625 35.8,93.375 cw(c35.725,93.375) 35.725,93.3
VP_4R8 on TOP "TOP12" (solid, pour order 51): 25 vertices, not listed, extent 33.8,93.3 36.2,95.8
SIG190 on TOP "TOP11" (solid, pour order 50): 35.175,92.3 cw(c35.175,92.375) 35.1,92.375 35.1,93.025 cw(c35.175,93.025) 35.175,93.1 35.725,93.1 cw(c35.725,93.025) 35.8,93.025 35.8,92.775 cw(c35.725,92.775) 35.725,92.7 35.35,92.7 35.35,92.375 cw(c35.275,92.375) 35.275,92.3
SIG190 on TOP "TOP10" (solid, pour order 49): 34.825,91.1 cw(c34.825,91.025) 34.9,91.025 34.9,90.375 cw(c34.825,90.375) 34.825,90.3 34.275,90.3 cw(c34.275,90.375) 34.2,90.375 34.2,90.625 cw(c34.275,90.625) 34.275,90.7 34.65,90.7 34.65,91.025 cw(c34.725,91.025) 34.725,91.1
VP_SW on TOP "TOP9" (solid, pour order 48): 35.725,90.1 cw(c35.725,90.025) 35.8,90.025 35.8,89.775 cw(c35.725,89.775) 35.725,89.7 35.3,89.7 35.3,89.375 cw(c35.225,89.375) 35.225,89.3 34.775,89.3 cw(c34.775,89.375) 34.7,89.375 34.7,89.7 34.275,89.7 cw(c34.275,89.775) 34.2,89.775 34.2,90.025 cw(c34.275,90.025) 34.275,90.1
SIG190 on TOP "TOP8" (solid, pour order 47): 26 vertices, not listed, extent 33.8,90.3 36.2,93.1
VINA on TOP "TOP7" (solid, pour order 46): 22 vertices, not listed, extent 39.4,97.25 40.6,101.2
SIG46 on TOP "TOP5" (solid, pour order 44): 40.825,91.1 cw(c40.825,91.025) 40.9,91.025 40.9,90.375 cw(c40.825,90.375) 40.825,90.3 40.275,90.3 cw(c40.275,90.375) 40.2,90.375 40.2,90.625 cw(c40.275,90.625) 40.275,90.7 40.65,90.7 40.65,91.025 cw(c40.725,91.025) 40.725,91.1
SIG46 on TOP "TOP4" (solid, pour order 43): 26 vertices, not listed, extent 39.8,90.3 42.2,93.1
SIG46 on TOP "TOP3" (solid, pour order 42): 41.175,92.3 cw(c41.175,92.375) 41.1,92.375 41.1,93.025 cw(c41.175,93.025) 41.175,93.1 41.725,93.1 cw(c41.725,93.025) 41.8,93.025 41.8,92.775 cw(c41.725,92.775) 41.725,92.7 41.35,92.7 41.35,92.375 cw(c41.275,92.375) 41.275,92.3
VINA on TOP "TOP2" (solid, pour order 41): 40.275,93.3 cw(c40.275,93.375) 40.2,93.375 40.2,93.625 cw(c40.275,93.625) 40.275,93.7 40.7,93.7 40.7,94.025 cw(c40.775,94.025) 40.775,94.1 41.225,94.1 cw(c41.225,94.025) 41.3,94.025 41.3,93.7 41.725,93.7 cw(c41.725,93.625) 41.8,93.625 41.8,93.375 cw(c41.725,93.375) 41.725,93.3
VINA on TOP "TOP1" (solid, pour order 40): 25 vertices, not listed, extent 39.8,93.3 42.2,95.8
GND on TOP "TOP27" (solid, pour order 66): 24 vertices, not listed, extent 30.6,109.2 33.25,111.5
VDD on TOP "TOP25" (solid, pour order 64): 22 vertices, not listed, extent 33.4,107.9 36.8,111.55
VDD on TOP "TOP22" (solid, pour order 61): 33.475,107.9 cw(c33.475,107.975) 33.4,107.975 33.4,109.625 cw(c33.475,109.625) 33.475,109.7 33.925,109.7 cw(c33.925,109.625) 34,109.625 34,109 34.525,109 cw(c34.525,108.925) 34.6,108.925 34.6,107.975 cw(c34.525,107.975) 34.525,107.9
GND on TOP "TOP20" (solid, pour order 59): 32.525,106.95 cw(c32.525,107.025) 32.45,107.025 32.45,109.575 cw(c32.525,109.575) 32.525,109.65 32.975,109.65 cw(c32.975,109.575) 33.05,109.575 33.05,107.025 cw(c32.975,107.025) 32.975,106.95
VDD on TOP "TOP29" (solid, pour order 68): 19 vertices, not listed, extent 66.15,108.2 69.35,122.6
VINB on TOP "TOP31" (solid, pour order 70): 26 vertices, not listed, extent 57.35,107.6 62.85,122.8
VINA on TOP "TOP30" (solid, pour order 69): 26 vertices, not listed, extent 48.55,107.6 55.75,122.8
GND on Mid-Layer 1 "MID155" (solid, pour order 39): 25 vertices, not listed, extent 20.5,20.5 104.5,127.5
GND on Mid-Layer 2 "MID256" (solid, pour order 38): 25 vertices, not listed, extent 20.5,20.5 104.5,127.5
LOADB on BOTTOM "BOTTOM87" (solid, pour order 32): 27 vertices, not listed, extent 70.15,25.2 81.65,37.4
GND on BOTTOM "BOTTOM86" (solid, pour order 31): 75.05,33.05 cw(c75.05,33.3) 74.8,33.3 74.8,33.9 cw(c74.9,33.9) 74.9,34 76.9,34 cw(c76.9,33.9) 77,33.9 77,33.3 cw(c76.75,33.3) 76.75,33.05
GND on BOTTOM "BOTTOM80" (solid, pour order 25): 47.05,28.05 cw(c47.05,28.3) 46.8,28.3 46.8,30.7 cw(c47.05,30.7) 47.05,30.95 48.75,30.95 cw(c48.75,30.7) 49,30.7 49,28.3 cw(c48.75,28.3) 48.75,28.05
GND on BOTTOM "BOTTOM79" (solid, pour order 24): 54.05,28.05 cw(c54.05,28.3) 53.8,28.3 53.8,30.7 cw(c54.05,30.7) 54.05,30.95 55.75,30.95 cw(c55.75,30.7) 56,30.7 56,28.3 cw(c55.75,28.3) 55.75,28.05
GND on BOTTOM "BOTTOM78" (solid, pour order 23): 61.05,28.05 cw(c61.05,28.3) 60.8,28.3 60.8,30.7 cw(c61.05,30.7) 61.05,30.95 62.75,30.95 cw(c62.75,30.7) 63,30.7 63,28.3 cw(c62.75,28.3) 62.75,28.05
GND on BOTTOM "BOTTOM77" (solid, pour order 22): 68.05,28.05 cw(c68.05,28.3) 67.8,28.3 67.8,30.7 cw(c68.05,30.7) 68.05,30.95 69.75,30.95 cw(c69.75,30.7) 70,30.7 70,28.3 cw(c69.75,28.3) 69.75,28.05
GND on BOTTOM "BOTTOM76" (solid, pour order 21): 75.05,28.05 cw(c75.05,28.3) 74.8,28.3 74.8,30.7 cw(c75.05,30.7) 75.05,30.95 76.75,30.95 cw(c76.75,30.7) 77,30.7 77,28.3 cw(c76.75,28.3) 76.75,28.05
GND on BOTTOM "BOTTOM75" (solid, pour order 20): 82.05,28.05 cw(c82.05,28.3) 81.8,28.3 81.8,30.7 cw(c82.05,30.7) 82.05,30.95 83.75,30.95 cw(c83.75,30.7) 84,30.7 84,28.3 cw(c83.75,28.3) 83.75,28.05
GND on BOTTOM "BOTTOM74" (solid, pour order 19): 89.05,28.05 cw(c89.05,28.3) 88.8,28.3 88.8,30.7 cw(c89.05,30.7) 89.05,30.95 90.75,30.95 cw(c90.75,30.7) 91,30.7 91,28.3 cw(c90.75,28.3) 90.75,28.05
LOADA on BOTTOM "BOTTOM73" (solid, pour order 18): 92.304,25.2 cw(c92.304,25.45) 92.127,25.273 91.223,26.177 cw(c91.4,26.354) 91.15,26.354 91.15,35.15 cw(c91.4,35.15) 91.4,35.4 95.4,35.4 cw(c95.4,35.15) 95.65,35.15 95.65,26.354 cw(c95.4,26.354) 95.577,26.177 94.673,25.273 cw(c94.496,25.45) 94.496,25.2
LOADC on BOTTOM "BOTTOM72" (solid, pour order 17): 64.304,25.2 cw(c64.304,25.45) 64.127,25.273 63.223,26.177 cw(c63.4,26.354) 63.15,26.354 63.15,35.15 cw(c63.4,35.15) 63.4,35.4 67.4,35.4 cw(c67.4,35.15) 67.65,35.15 67.65,26.354 cw(c67.4,26.354) 67.577,26.177 66.673,25.273 cw(c66.496,25.45) 66.496,25.2
LOADA on BOTTOM "BOTTOM71" (solid, pour order 16): 85.304,25.2 cw(c85.304,25.45) 85.127,25.273 84.223,26.177 cw(c84.4,26.354) 84.15,26.354 84.15,35.15 cw(c84.4,35.15) 84.4,35.4 88.4,35.4 cw(c88.4,35.15) 88.65,35.15 88.65,26.354 cw(c88.4,26.354) 88.577,26.177 87.673,25.273 cw(c87.496,25.45) 87.496,25.2
LOADC on BOTTOM "BOTTOM70" (solid, pour order 15): 57.304,25.2 cw(c57.304,25.45) 57.127,25.273 56.223,26.177 cw(c56.4,26.354) 56.15,26.354 56.15,35.15 cw(c56.4,35.15) 56.4,35.4 60.4,35.4 cw(c60.4,35.15) 60.65,35.15 60.65,26.354 cw(c60.4,26.354) 60.577,26.177 59.673,25.273 cw(c59.496,25.45) 59.496,25.2
LOADD on BOTTOM "BOTTOM69" (solid, pour order 14): 43.304,25.2 cw(c43.304,25.45) 43.127,25.273 42.223,26.177 cw(c42.4,26.354) 42.15,26.354 42.15,35.15 cw(c42.4,35.15) 42.4,35.4 46.4,35.4 cw(c46.4,35.15) 46.65,35.15 46.65,26.354 cw(c46.4,26.354) 46.577,26.177 45.673,25.273 cw(c45.496,25.45) 45.496,25.2
LOADD on BOTTOM "BOTTOM68" (solid, pour order 13): 50.304,25.2 cw(c50.304,25.45) 50.127,25.273 49.223,26.177 cw(c49.4,26.354) 49.15,26.354 49.15,35.15 cw(c49.4,35.15) 49.4,35.4 53.4,35.4 cw(c53.4,35.15) 53.65,35.15 53.65,26.354 cw(c53.4,26.354) 53.577,26.177 52.673,25.273 cw(c52.496,25.45) 52.496,25.2
VOUT on BOTTOM "BOTTOM91" (solid, pour order 36): 49 vertices, not listed, extent 45,42 84,89.45
VP_4R8 on BOTTOM "BOTTOM66" (solid, pour order 11): 75 vertices, not listed, extent 74.8,37.6 100.4,76
VP_4R8 on BOTTOM "BOTTOM63" (solid, pour order 8): 35 vertices, not listed, extent 72.8,57.2 77.275,73.675
VP_4R8 on BOTTOM "BOTTOM62" (solid, pour order 7): 25 vertices, not listed, extent 86.2,66.2 93,69.6
VP_4R8 on BOTTOM "BOTTOM61" (solid, pour order 6): 25 vertices, not listed, extent 86.2,57.4 92.8,61.8
VP_4R8 on BOTTOM "BOTTOM88" (solid, pour order 33): 71 vertices, not listed, extent 28.8,37.6 45.4,58
VP_4R8 on BOTTOM "BOTTOM60" (solid, pour order 5): 25 vertices, not listed, extent 40.2,66.2 47,69.6
VP_4R8 on BOTTOM "BOTTOM59" (solid, pour order 4): 25 vertices, not listed, extent 40.2,57.4 46.8,61.8
VOUT on BOTTOM "BOTTOM58" (solid, pour order 3): 55.55,89.45 cw(c55.55,89.2) 55.8,89.2 55.8,88.3 cw(c55.55,88.3) 55.55,88.05 52.25,88.05 cw(c52.25,88.3) 52,88.3 52,89.2 cw(c52.25,89.2) 52.25,89.45
VDD on BOTTOM "BOTTOM82" (solid, pour order 27): 19 vertices, not listed, extent 34,108.2 69.35,111.9
VINB on BOTTOM "BOTTOM81" (solid, pour order 26): 26 vertices, not listed, extent 57.3,95.75 79.4,109.2
VINB on BOTTOM "BOTTOM64" (solid, pour order 9): 69.45,95.75 cw(c69.45,96) 69.2,96 69.2,96.9 cw(c69.45,96.9) 69.45,97.15 72.75,97.15 cw(c72.75,96.9) 73,96.9 73,96 cw(c72.75,96) 72.75,95.75
GND on BOTTOM "BOTTOM65" (solid, pour order 10): 40.75,104.6 ccw(c41,104.6) 41.25,104.6 ccw(c41,104.6)
VINA on BOTTOM "BOTTOM57" (solid, pour order 2): 52.25,95.75 cw(c52.25,96) 52,96 52,96.9 cw(c52.25,96.9) 52.25,97.15 55.55,97.15 cw(c55.55,96.9) 55.8,96.9 55.8,96 cw(c55.55,96) 55.55,95.75
VINB on BOTTOM "BOTTOM85" (solid, pour order 30): 59,112.7 cw(c59,112.95) 58.75,112.95 58.75,122.725 cw(c58.825,122.725) 58.825,122.8 62.55,122.8 cw(c62.55,122.55) 62.8,122.55 62.8,112.95 cw(c62.55,112.95) 62.55,112.7
VINA on BOTTOM "BOTTOM67" (solid, pour order 12): 51,112.7 cw(c51,112.95) 50.75,112.95 50.75,114.896 cw(c51,114.896) 50.823,115.073 51.677,115.927 ccw(c51.5,116.104) 51.75,116.104 51.75,122.55 cw(c52,122.55) 52,122.8 55.5,122.8 cw(c55.5,122.55) 55.75,122.55 55.75,112.95 cw(c55.5,112.95) 55.5,112.7
VINA on BOTTOM "BOTTOM83" (solid, pour order 28): 45 vertices, not listed, extent 38.8,94.175 56.8,109.2
GND on BOTTOM "BOTTOM84" (solid, pour order 29): 49.25,102 ccw(c49.5,102) 49.75,102 ccw(c49.5,102)
VP_4R8 on BOTTOM "BOTTOM89" (solid, pour order 34): 76 vertices, not listed, extent 27.4,57 55,104.4
VP_4R8 on BOTTOM "BOTTOM90" (solid, pour order 35): 35 vertices, not listed, extent 26.8,57.2 32,74.2
GND on BOTTOM "BOTTOM92" (solid, pour order 37): 25 vertices, not listed, extent 20.5,20.5 104.5,127.5

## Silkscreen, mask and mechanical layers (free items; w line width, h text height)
Top Overlay:
  lines w0.2: 21,53.2 21.6,53.2 21.6,53.8 ; 21.6,78.2 20.6,77.2 20.6,57 20.6,55 20.6,54.2 20.8,54 22,52.8 ; 31.4,46.2 31.4,46.5 32,47.1 32,48.5 ; 33.6,43.7 34.2,43.1 34.2,42.7 ; 34,46.6 34.3,46.3 34.3,45.1 ; 40.8,22 40.8,23.4 ; 40.8,22.8 43.8,22.8 ; 44.4,23.4 44.4,22 45,22 ; 45,22.8 47.9,22.8 47.9,23.4 ; 50.6,22 51.4,22 51.4,23.4 ; 52.5,83.748 52.5,82.65 72.5,82.65 72.5,83.748 ; 52.5,101.552 52.5,102.65 72.5,102.65 72.5,101.552 ; 54.8,22 54.8,23.4 ; 54.8,22.8 57.8,22.8 ; 58.4,23.4 58.4,22 59,22 ; 59,22.8 61.9,22.8 61.9,23.4 ; 64.6,22 65.4,22 65.4,23.4 ; 68.8,22 68.8,23.4 ; 68.8,22.8 71.8,22.8 ; 72.4,23.4 72.4,22 73,22 ; 73,22.8 75.9,22.8 75.9,23.4 ; 78.6,22 79.4,22 79.4,23.4 ; 82.2,81.6 102.6,81.6 ; 83.6,22 83.6,23.4 ; 83.6,22.8 85.8,22.8 ; 86.4,23.4 86.4,22 87,22 ; 87,22.8 89.9,22.8 89.9,23.4 ; 87.8,43 88.4,42.4 ; 92.2,53.4 92.4,53.2 94.3,53.2 94.7,53.6 95.6,53.6 ; 92.6,22 93.4,22 93.4,23.4
  lines w0.3: 24.6,80.6 24.6,83 ; 91.406,102.487 93.806,102.487
  text "VINA" at 50.69,125.06 h0.71
  text "GND" at 55.34,125.06 h0.71
  text "VINB" at 59.09,125.06 h0.71
  text "GND" at 63.74,125.06 h0.71
  text "VDD" at 67.54,125.06 h0.71
  text "GND" at 71.34,125.06 h0.71
  text "MUX 1/2/3/5/6" at 88.176,106.807 h0.71
  text "setting" at 90.97,105.308 h0.71
  text "BBM" at 86.305,101.775 h1.35
  text "MBB" at 95.505,101.775 h1.35
  text "VINB" at 76.29,97.06 h0.71
  text "LOAD-D" at 23.8,89.154 h0.71
  text "setting" at 23.825,87.897 h0.71
  text "GND" at 45.74,86.46 h0.71
  text "Multiplexer" at 84.48,85.522 h1.35
  text "DC" at 23.076,83.68 h1.35
  text "！" at 28.448,83.642 h2.5
  text "△" at 26.53,82.88 h5
  text "Base Board" at 84.455,82.626 h1.35
  text "RD221" at 82.575,80.086 h0.71
  text "Gate Driver IC for" at 82.525,78.664 h0.71
  text "PULSE" at 23.266,77.953 h1.35
  text "Common Drain MOSFET" at 82.55,77.254 h0.71
  text "VOUT" at 45.29,77.06 h0.71
  text "GND" at 29.74,21.26 h0.71
  text "FLAG" at 33.29,21.26 h0.71
  text "LOADD" at 45.64,21.26 h0.71
  text "LOADC" at 59.64,21.26 h0.71
  text "LOADB" at 73.64,21.26 h0.71
  text "LOADA" at 87.84,21.26 h0.71
  text "GND" at 39.34,20.46 h0.71
  text "GND" at 53.34,20.46 h0.71
  text "GND" at 68.34,20.46 h0.71
  text "GND" at 83.14,20.46 h0.71
Bottom Overlay:
  lines w0.2: 28.75,36.8 29.9,36.8 29.9,38.2 ; 30.6,33.2 31.25,33.2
